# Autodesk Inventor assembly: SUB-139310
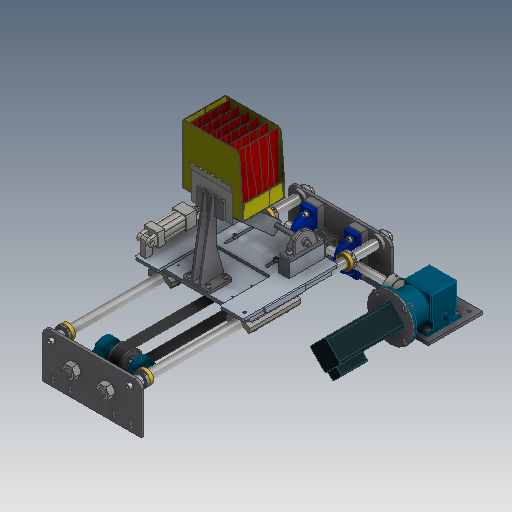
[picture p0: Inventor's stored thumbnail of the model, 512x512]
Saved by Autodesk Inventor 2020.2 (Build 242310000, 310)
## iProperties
Created: 1999-11
Part Number: SUB-139310
Document SubType Name: Assembly
Designer: sspink
Mass: 64674.3 g
Surface Area: 32419.9 cm^2
Volume: 15890.5 cm^3
Density: 4.07001 g/cm^3
Control State: 0
Master: False
Checked Out: False
Shininess: 0.0
Length Units: 11269
Angle Units: 11279
Time Units: 11290
Mass Units: 11283
Length Display Precision: 3
Angle Display Precision: 2
Compacted: True
Dimensions: 657,1x1021,6x696,7 mm
Mass: 64,674 kg
DocNumber: SUB-139310.iam
Folder: 01 - Themengebiete\Simplification\01 - Packaging machine\
VDS_Category: 3D Komponenten
Density: 0.0
Volumn: 0.0
Area: 0.0
PropertySet Name: Model Information
Author: sspink
Revision Number: -
Title: SUB-139310
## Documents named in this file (46)
- D:\07 - DEMODATEN\OTX 2019 - Dataset - UPDATE - Dez2019\Designs\07-Packing machine\SUB-139310.iam
- D:\07 - DEMODATEN\OTX 2019 - Dataset - UPDATE - Dez2019\Designs\07-Packing machine\500397.iam
- D:\07 - DEMODATEN\OTX 2019 - Dataset - UPDATE - Dez2019\Designs\07-Packing machine\Parts\ADSK-011320.ipt
- D:\07 - DEMODATEN\OTX 2019 - Dataset - UPDATE - Dez2019\Designs\07-Packing machine\Parts\ADSK-011732.ipt
- D:\07 - DEMODATEN\OTX 2019 - Dataset - UPDATE - Dez2019\Designs\07-Packing machine\Parts\ADSK-011289.ipt
- D:\07 - DEMODATEN\OTX 2019 - Dataset - UPDATE - Dez2019\Designs\07-Packing machine\Parts\ADSK-011687.ipt
- D:\07 - DEMODATEN\OTX 2019 - Dataset - UPDATE - Dez2019\Designs\07-Packing machine\500178.iam
- D:\07 - DEMODATEN\OTX 2019 - Dataset - UPDATE - Dez2019\Designs\07-Packing machine\Parts\ADSK-011294.ipt
- D:\07 - DEMODATEN\OTX 2019 - Dataset - UPDATE - Dez2019\Designs\07-Packing machine\A103577.iam
- D:\07 - DEMODATEN\OTX 2019 - Dataset - UPDATE - Dez2019\Designs\07-Packing machine\Parts\ADSK-011304.ipt
- D:\07 - DEMODATEN\OTX 2019 - Dataset - UPDATE - Dez2019\Designs\07-Packing machine\Parts\ADSK-011305.ipt
- D:\07 - DEMODATEN\OTX 2019 - Dataset - UPDATE - Dez2019\Designs\07-Packing machine\Parts\ADSK-011715.ipt
- D:\07 - DEMODATEN\OTX 2019 - Dataset - UPDATE - Dez2019\Designs\07-Packing machine\Parts\ADSK-011313.ipt
- D:\07 - DEMODATEN\OTX 2019 - Dataset - UPDATE - Dez2019\Designs\07-Packing machine\Parts\ADSK-011314.ipt
- D:\07 - DEMODATEN\OTX 2019 - Dataset - UPDATE - Dez2019\Designs\07-Packing machine\Parts\ADSK-011773.ipt
- D:\07 - DEMODATEN\OTX 2019 - Dataset - UPDATE - Dez2019\Designs\07-Packing machine\Parts\ADSK-011319.ipt
- D:\07 - DEMODATEN\OTX 2019 - Dataset - UPDATE - Dez2019\Designs\07-Packing machine\Parts\ADSK-011765.ipt
- D:\07 - DEMODATEN\OTX 2019 - Dataset - UPDATE - Dez2019\Designs\07-Packing machine\Parts\ADSK-011341.ipt
- D:\07 - DEMODATEN\OTX 2019 - Dataset - UPDATE - Dez2019\Designs\07-Packing machine\A103689.iam
- D:\07 - DEMODATEN\OTX 2019 - Dataset - UPDATE - Dez2019\Designs\07-Packing machine\Parts\ADSK-011342.ipt
- D:\07 - DEMODATEN\OTX 2019 - Dataset - UPDATE - Dez2019\Designs\07-Packing machine\Parts\ADSK-011753.ipt
- D:\07 - DEMODATEN\OTX 2019 - Dataset - UPDATE - Dez2019\Designs\07-Packing machine\Parts\ADSK-011234.ipt
- D:\07 - DEMODATEN\OTX 2019 - Dataset - UPDATE - Dez2019\Content Center Files\de-DE\DIN 125-1  B\DIN 125-1 - B 13.ipt
- D:\07 - DEMODATEN\OTX 2019 - Dataset - UPDATE - Dez2019\Content Center Files\de-DE\ISO 4762(2)\ISO 4762 - M12 x 25ISO.ipt
- D:\07 - DEMODATEN\OTX 2019 - Dataset - UPDATE - Dez2019\Content Center Files\de-DE\ISO 4762(2)\ISO 4762 - M6 x 20ISO.ipt
- D:\07 - DEMODATEN\OTX 2019 - Dataset - UPDATE - Dez2019\Designs\07-Packing machine\ADSK-014169.iam
- D:\07 - DEMODATEN\OTX 2019 - Dataset - UPDATE - Dez2019\Content Center Files\de-DE\DIN 125-1  B\DIN 125-1 - B 8,4.ipt
- D:\07 - DEMODATEN\OTX 2019 - Dataset - UPDATE - Dez2019\Content Center Files\de-DE\ISO 4762(2)\ISO 4762 - M8 x 20ISO.ipt
- D:\07 - DEMODATEN\OTX 2019 - Dataset - UPDATE - Dez2019\Content Center Files\de-DE\ISO 10642(1)\ISO 10642 - M6x10.ipt
- D:\07 - DEMODATEN\OTX 2019 - Dataset - UPDATE - Dez2019\Content Center Files\de-DE\DIN 125-1  B\DIN 125-1 - B 10,5.ipt
- D:\07 - DEMODATEN\OTX 2019 - Dataset - UPDATE - Dez2019\Content Center Files\de-DE\ISO 4762(2)\ISO 4762 - M10 x 30ISO.ipt
- D:\07 - DEMODATEN\OTX 2019 - Dataset - UPDATE - Dez2019\Content Center Files\de-DE\ISO 10642(1)\ISO 10642 - M8x20.ipt
- D:\07 - DEMODATEN\OTX 2019 - Dataset - UPDATE - Dez2019\Content Center Files\de-DE\ISO 4032(1)\ISO 4032 - M30DIN EN.ipt
- D:\07 - DEMODATEN\OTX 2019 - Dataset - UPDATE - Dez2019\Content Center Files\de-DE\ISO 2491 - A\ISO 2491 - A  6 x 4 x 32.ipt
- D:\07 - DEMODATEN\OTX 2019 - Dataset - UPDATE - Dez2019\Content Center Files\de-DE\ISO 2491 - A\ISO 2491 - A  6 x 4 x 28.ipt
- D:\07 - DEMODATEN\OTX 2019 - Dataset - UPDATE - Dez2019\Content Center Files\de-DE\ISO 10642(1)\ISO 10642 - M10x25.ipt
- D:\07 - DEMODATEN\OTX 2019 - Dataset - UPDATE - Dez2019\Content Center Files\de-DE\ISO 4032(1)\ISO 4032 - M10DIN EN.ipt
- D:\07 - DEMODATEN\OTX 2019 - Dataset - UPDATE - Dez2019\Designs\07-Packing machine\ADSK-014170.iam
- D:\07 - DEMODATEN\OTX 2019 - Dataset - UPDATE - Dez2019\Content Center Files\de-DE\ISO 2491 - A\ISO 2491 - A  6 x 4 x 40.ipt
- D:\07 - DEMODATEN\OTX 2019 - Dataset - UPDATE - Dez2019\Content Center Files\de-DE\ISO 4028\ISO 4028 - M8 x 20 - ISO.ipt
- D:\07 - DEMODATEN\OTX 2019 - Dataset - UPDATE - Dez2019\Content Center Files\de-DE\ISO 4028\ISO 4028 - M8 x 16 - ISO.ipt
- D:\07 - DEMODATEN\OTX 2019 - Dataset - UPDATE - Dez2019\Content Center Files\de-DE\ISO 4032(1)\ISO 4032 - M8DIN EN.ipt
- D:\07 - DEMODATEN\OTX 2019 - Dataset - UPDATE - Dez2019\Content Center Files\de-DE\ISO 4762(2)\ISO 4762 - M8 x 35ISO.ipt
- D:\07 - DEMODATEN\OTX 2019 - Dataset - UPDATE - Dez2019\Content Center Files\de-DE\ISO 4028\ISO 4028 - M5 x 10 - ISO.ipt
- D:\07 - DEMODATEN\OTX 2019 - Dataset - UPDATE - Dez2019\Designs\07-Packing machine\Parts\GMI 17 oz Pouch Tray.ipt
- GMI 17 oz Pouch Tray.ipt
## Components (119 placed, 44 different names)
1. ADSK-011319:1 — Insert:6, Insert:7, Mate:22, Mate:24, Flush:6
2. ADSK-011289:1 — Insert:7, Mate:17, Mate:47, Mate:49, Passend:56, Tangential:4
3. ADSK-011289:2 — Insert:6, Mate:16, Mate:46, Mate:48, Passend:55, Tangential:5
4. 500178:1 [sub-assembly] — Passend:60, Passend:61, Passend:62, Passend:63, Passend:64, Passend:65, Passend:68, Passend:70, Passend:72, Passend:74
5. ADSK-011294:1 — Passend:63, Passend:64, Passend:65, Passend:76, Passend:77, Passend:78, Passend:159
6. ADSK-011304:1 — Mate:5, Mate:7, Passend:15, Mate:25, Passend:112, Fluchtend:82, Passend:114, Passend:115, Passend:136, Passend:138, Fluchtend:89, Passend:141, Passend:142, Tangential:2
7. ADSK-011305:1 — Mate:32, Flush:5, Passend:130, Passend:132, Passend:133, Passend:135
8. ADSK-011715:3 — Mate:25, Mate:29, Passend:30, Passend:92, Passend:94, Passend:140
9. ADSK-011715:4 — Passend:15, Mate:28, Passend:31, Passend:88, Passend:90, Passend:139
10. ADSK-011314:1 — Insert:8, Mate:24, Flush:4
11. ADSK-011314:2 — Mate:22, Insert:21, Flush:4, Passend:107
12. ADSK-011773:1 — Insert:8, Flush:5
13. ADSK-011773:2 — Mate:32, Insert:21
14. ADSK-011313:1 — Mate:16, Mate:17, Insert:17, Insert:18, Insert:19, Insert:20, Flush:6, Insert:23, Insert:24, Insert:25, Insert:26, Passend:156, Passend:157
15. ADSK-011320:1 — Insert:19, Insert:20, Mate:28, Passend:139
16. ADSK-011320:2 — Insert:17, Insert:18, Mate:29, Passend:30, Passend:140
17. A103577:1 [sub-assembly] — Mate:1, Mate:2, Mate:3, Mate:4, Mate:6, Insert:1, Insert:15, Insert:16, Passend:143, Winkel:1, Passend:144, Passend:145, Tangential:3
18. ADSK-011765:1 — Insert:1
19. ADSK-011341:1 — Insert:13, Insert:14, Insert:15, Insert:16
20. A103689:1 [sub-assembly] — Insert:13, Insert:14
21. ADSK-011342:1 — Mate:1, Mate:2, Mate:3, Passend:143, Passend:144, Passend:145, Passend:149, Passend:151, Passend:153, Passend:155
22. ADSK-011753:1 — Mate:4, Mate:5, Mate:6, Mate:7, Fluchtend:82, Passend:116, Passend:146, Passend:147
23. ADSK-011234:1 — Passend:108, Fluchtend:86, Passend:131, Passend:137, Fluchtend:87, Fluchtend:89
24. 500397:1 [sub-assembly] — Passend:80, Fluchtend:81, Passend:82, Passend:84, Passend:108, Fluchtend:88, Passend:158, Tangential:6
25. ADSK-011732:1 — Insert:26
26. ADSK-011732:2 — Insert:23, Einfügen:40
27. ADSK-011732:3 — Insert:24, Einfügen:41
28. ADSK-011732:4 — Insert:25, Einfügen:42
29. ADSK-011732:5 — Mate:46, Flush:13, Insert:31, Einfügen:43
30. ADSK-011732:6 — Mate:47, Flush:13, Insert:32
31. ADSK-011732:7 — Mate:49, Flush:14, Insert:29
32. ADSK-011732:8 — Mate:48, Flush:14, Insert:30
33. GMI 17 oz Pouch Tray:2 — Passend:158, Passend:159, Tangential:6
34. ADSK-011687:1 — Insert:30
35. ADSK-011687:2 — Insert:29
36. ADSK-011687:3 — Insert:31
37. ADSK-011687:4 — Insert:32
38. ADSK-014169:1 [sub-assembly] — Passend:55, Passend:56, Passend:60, Passend:61, Passend:62, Passend:80, Fluchtend:81, Fluchtend:88
39. ADSK-014170:1 [sub-assembly] — Passend:130, Fluchtend:86, Passend:131, Passend:134, Passend:135
40. ADSK-014170:2 [sub-assembly] — Passend:136, Passend:137, Fluchtend:87, Passend:138
41. DIN 125-1 B B 8,4:7 — Passend:149
42. DIN 125-1 B B 8,4:8 — Passend:151
43. DIN 125-1 B B 8,4:9 — Passend:153
44. DIN 125-1 B B 8,4:10 — Passend:155
45. DIN 125-1 B B 8,4:11
46. DIN 125-1 B B 8,4:12
47. DIN 125-1 B B 8,4:13
48. DIN 125-1 B B 8,4:14
49. DIN EN 24032 M8:1
50. DIN EN 24032 M8:2
51. DIN EN 24032 M8:3
52. DIN EN 24032 M8:4
53. ISO 4762 M8 x 35:1
54. ISO 4762 M8 x 35:2
55. ISO 4762 M8 x 35:3
56. ISO 4762 M8 x 35:4
57. ISO 4028 M5 x 10:1 — Passend:156, Tangential:4
58. ISO 4028 M5 x 10:2 — Passend:157, Tangential:5
59. ISO 4028 M8 x 20:1 — Passend:146, Tangential:2
60. ISO 4028 M8 x 16:1 — Passend:147, Tangential:3
61. ISO 2491 A A  6 x 4 x 32:2 — Passend:132, Passend:133, Passend:134
62. DIN 125-1 B B 8,4:1 — Passend:68
63. DIN 125-1 B B 8,4:2 — Passend:70
64. DIN 125-1 B B 8,4:3 — Passend:72
65. DIN 125-1 B B 8,4:4 — Passend:74
66. ISO 4762 M8 x 20:1
67. ISO 4762 M8 x 20:2
68. ISO 4762 M8 x 20:3
69. ISO 4762 M8 x 20:4
70. ISO 10642 M6x10:1
71. ISO 10642 M6x10:2 — Passend:77
72. ISO 10642 M6x10:3 — Passend:76
73. ISO 10642 M6x10:4 — Passend:78
74. DIN 125-1 B B 8,4:5 — Passend:82
75. DIN 125-1 B B 8,4:6 — Passend:84, Passend:86
76. ISO 4762 M8 x 20:5 — Passend:86
77. ISO 4762 M8 x 20:6
78. DIN 125-1 B B 10,5:1 — Passend:88, Passend:96, Passend:98
79. DIN 125-1 B B 10,5:2 — Passend:90
80. DIN 125-1 B B 10,5:3 — Passend:92, Passend:100, Passend:102
81. DIN 125-1 B B 10,5:4 — Passend:94
82. ISO 4762 M10 x 30:1 — Passend:96
83. ISO 4762 M10 x 30:2 — Passend:98, Passend:31
84. ISO 4762 M10 x 30:3 — Passend:100
85. ISO 4762 M10 x 30:4 — Passend:102
86. ISO 10642 M8x20:1
87. ISO 10642 M8x20:2
88. ISO 10642 M8x20:3
89. ISO 10642 M8x20:4
90. DIN EN 24032 M30:1
91. DIN EN 24032 M30:2 — Passend:107
92. DIN EN 24032 M30:3
93. DIN EN 24032 M30:4
94. ISO 2491 A A  6 x 4 x 40:1 — Passend:112, Passend:141, Passend:142
95. ISO 2491 A A  6 x 4 x 28:1 — Passend:114, Passend:115, Passend:116
96. ISO 10642 M10x25:1
97. ISO 10642 M10x25:2
98. ISO 10642 M10x25:3
99. ISO 10642 M10x25:4
100. DIN 125-1 B B 10,5:5 — Passend:124
101. DIN 125-1 B B 10,5:6
102. DIN 125-1 B B 10,5:7
103. DIN 125-1 B B 10,5:8
104. DIN EN 24032 M10:1 — Passend:124
105. DIN EN 24032 M10:2
106. DIN EN 24032 M10:3
107. DIN EN 24032 M10:4
108. DIN 125-1 B B 13:1 — Passend:54
109. DIN 125-1 B B 13:2
110. ISO 4762 M12 x 25:1 — Passend:54
111. ISO 4762 M12 x 25:2
112. ISO 4762 M6 x 20:1
113. ISO 4762 M6 x 20:2
114. ISO 4762 M6 x 20:3
115. ISO 4762 M6 x 20:4
116. ISO 4762 M6 x 20:5 — Einfügen:40
117. ISO 4762 M6 x 20:6 — Einfügen:41
118. ISO 4762 M6 x 20:7 — Einfügen:42
119. ISO 4762 M6 x 20:8 — Einfügen:43
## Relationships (125: Mate 83, Insert 25, Flush 11, Tangent 5, Angle 1)
- Mate:1: A103577:1 ↔ ADSK-011342:1
- Mate:2: A103577:1 ↔ ADSK-011342:1
- Mate:3: A103577:1 ↔ ADSK-011342:1
- Mate:4: A103577:1 ↔ ADSK-011753:1
- Mate:5: ADSK-011304:1 ↔ ADSK-011753:1
- Mate:6: A103577:1 ↔ ADSK-011753:1
- Mate:7: ADSK-011304:1 ↔ ADSK-011753:1
- Insert:1: A103577:1 ↔ ADSK-011765:1
- Insert:6: ADSK-011319:1 ↔ ADSK-011289:2
- Insert:7: ADSK-011319:1 ↔ ADSK-011289:1
- Insert:8: ADSK-011314:1 ↔ ADSK-011773:1
- Passend:15 [Mate]: ADSK-011304:1 ↔ ADSK-011715:4
- Mate:16: ADSK-011289:2 ↔ ADSK-011313:1
- Mate:17: ADSK-011289:1 ↔ ADSK-011313:1
- Mate:22: ADSK-011319:1 ↔ ADSK-011314:2
- Mate:24: ADSK-011319:1 ↔ ADSK-011314:1
- Mate:25: ADSK-011304:1 ↔ ADSK-011715:3
- Insert:13: ADSK-011341:1 ↔ A103689:1
- Insert:14: ADSK-011341:1 ↔ A103689:1
- Insert:15: A103577:1 ↔ ADSK-011341:1
- Insert:16: A103577:1 ↔ ADSK-011341:1
- Insert:17: ADSK-011313:1 ↔ ADSK-011320:2
- Insert:18: ADSK-011313:1 ↔ ADSK-011320:2
- Insert:19: ADSK-011313:1 ↔ ADSK-011320:1
- Insert:20: ADSK-011313:1 ↔ ADSK-011320:1
- Mate:28: ADSK-011715:4 ↔ ADSK-011320:1
- Mate:29: ADSK-011715:3 ↔ ADSK-011320:2
- Passend:30 [Mate]: ADSK-011715:3 ↔ ADSK-011320:2
- Passend:31 [Mate]: ADSK-011715:4 ↔ ISO 4762 M10 x 30:2
- Mate:32: ADSK-011305:1 ↔ ADSK-011773:2
- Insert:21: ADSK-011314:2 ↔ ADSK-011773:2
- Flush:4: ADSK-011314:1 ↔ ADSK-011314:2
- Flush:5: ADSK-011305:1 ↔ ADSK-011773:1
- Flush:6: ADSK-011319:1 ↔ ADSK-011313:1
- Insert:23: ADSK-011313:1 ↔ ADSK-011732:2
- Insert:24: ADSK-011313:1 ↔ ADSK-011732:3
- Insert:25: ADSK-011313:1 ↔ ADSK-011732:4
- Insert:26: ADSK-011313:1 ↔ ADSK-011732:1
- Mate:46: ADSK-011289:2 ↔ ADSK-011732:5
- Mate:47: ADSK-011289:1 ↔ ADSK-011732:6
- Flush:13: ADSK-011732:5 ↔ ADSK-011732:6
- Mate:48: ADSK-011289:2 ↔ ADSK-011732:8
- Mate:49: ADSK-011289:1 ↔ ADSK-011732:7
- Flush:14: ADSK-011732:7 ↔ ADSK-011732:8
- Insert:29: ADSK-011732:7 ↔ ADSK-011687:2
- Insert:30: ADSK-011732:8 ↔ ADSK-011687:1
- Insert:31: ADSK-011732:5 ↔ ADSK-011687:3
- Insert:32: ADSK-011732:6 ↔ ADSK-011687:4
- Passend:54 [Mate]: DIN 125-1 B B 13:1 ↔ ISO 4762 M12 x 25:1
- Einfügen:40 [Insert]: ADSK-011732:2 ↔ ISO 4762 M6 x 20:5
- Einfügen:41 [Insert]: ADSK-011732:3 ↔ ISO 4762 M6 x 20:6
- Einfügen:42 [Insert]: ADSK-011732:4 ↔ ISO 4762 M6 x 20:7
- Einfügen:43 [Insert]: ADSK-011732:5 ↔ ISO 4762 M6 x 20:8
- Passend:55 [Mate]: ADSK-011289:2 ↔ ADSK-014169:1
- Passend:56 [Mate]: ADSK-011289:1 ↔ ADSK-014169:1
- Passend:60 [Mate]: 500178:1 ↔ ADSK-014169:1
- Passend:61 [Mate]: 500178:1 ↔ ADSK-014169:1
- Passend:62 [Mate]: 500178:1 ↔ ADSK-014169:1
- Passend:63 [Mate]: 500178:1 ↔ ADSK-011294:1
- Passend:64 [Mate]: 500178:1 ↔ ADSK-011294:1
- Passend:65 [Mate]: 500178:1 ↔ ADSK-011294:1
- Passend:68 [Mate]: 500178:1 ↔ DIN 125-1 B B 8,4:1
- Passend:70 [Mate]: 500178:1 ↔ DIN 125-1 B B 8,4:2
- Passend:72 [Mate]: 500178:1 ↔ DIN 125-1 B B 8,4:3
- Passend:74 [Mate]: 500178:1 ↔ DIN 125-1 B B 8,4:4
- Passend:76 [Mate]: ADSK-011294:1 ↔ ISO 10642 M6x10:3
- Passend:77 [Mate]: ADSK-011294:1 ↔ ISO 10642 M6x10:2
- Passend:78 [Mate]: ADSK-011294:1 ↔ ISO 10642 M6x10:4
- Passend:80 [Mate]: 500397:1 ↔ ADSK-014169:1
- Fluchtend:81 [Flush]: 500397:1 ↔ ADSK-014169:1
- Passend:82 [Mate]: 500397:1 ↔ DIN 125-1 B B 8,4:5
- Passend:84 [Mate]: 500397:1 ↔ DIN 125-1 B B 8,4:6
- Passend:86 [Mate]: DIN 125-1 B B 8,4:6 ↔ ISO 4762 M8 x 20:5
- Passend:88 [Mate]: ADSK-011715:4 ↔ DIN 125-1 B B 10,5:1
- Passend:90 [Mate]: ADSK-011715:4 ↔ DIN 125-1 B B 10,5:2
- Passend:92 [Mate]: ADSK-011715:3 ↔ DIN 125-1 B B 10,5:3
- Passend:94 [Mate]: ADSK-011715:3 ↔ DIN 125-1 B B 10,5:4
- Passend:96 [Mate]: DIN 125-1 B B 10,5:1 ↔ ISO 4762 M10 x 30:1
- Passend:98 [Mate]: DIN 125-1 B B 10,5:1 ↔ ISO 4762 M10 x 30:2
- Passend:100 [Mate]: DIN 125-1 B B 10,5:3 ↔ ISO 4762 M10 x 30:3
- Passend:102 [Mate]: DIN 125-1 B B 10,5:3 ↔ ISO 4762 M10 x 30:4
- Passend:107 [Mate]: ADSK-011314:2 ↔ DIN EN 24032 M30:2
- Passend:108 [Mate]: ADSK-011234:1 ↔ 500397:1
- Passend:112 [Mate]: ADSK-011304:1 ↔ ISO 2491 A A  6 x 4 x 40:1
- Fluchtend:82 [Flush]: ADSK-011304:1 ↔ ADSK-011753:1
- Passend:114 [Mate]: ADSK-011304:1 ↔ ISO 2491 A A  6 x 4 x 28:1
- Passend:115 [Mate]: ADSK-011304:1 ↔ ISO 2491 A A  6 x 4 x 28:1
- Passend:116 [Mate]: ADSK-011753:1 ↔ ISO 2491 A A  6 x 4 x 28:1
- Passend:124 [Mate]: DIN 125-1 B B 10,5:5 ↔ DIN EN 24032 M10:1
- Passend:130 [Mate]: ADSK-011305:1 ↔ ADSK-014170:1
- Fluchtend:86 [Flush]: ADSK-011234:1 ↔ ADSK-014170:1
- Passend:131 [Mate]: ADSK-011234:1 ↔ ADSK-014170:1
- Passend:132 [Mate]: ADSK-011305:1 ↔ ISO 2491 A A  6 x 4 x 32:2
- Passend:133 [Mate]: ADSK-011305:1 ↔ ISO 2491 A A  6 x 4 x 32:2
- Passend:134 [Mate]: ADSK-014170:1 ↔ ISO 2491 A A  6 x 4 x 32:2
- Passend:135 [Mate]: ADSK-011305:1 ↔ ADSK-014170:1
- Passend:136 [Mate]: ADSK-011304:1 ↔ ADSK-014170:2
- Passend:137 [Mate]: ADSK-011234:1 ↔ ADSK-014170:2
- Fluchtend:87 [Flush]: ADSK-011234:1 ↔ ADSK-014170:2
- Passend:138 [Mate]: ADSK-011304:1 ↔ ADSK-014170:2
- Passend:139 [Mate]: ADSK-011715:4 ↔ ADSK-011320:1
- Passend:140 [Mate]: ADSK-011715:3 ↔ ADSK-011320:2
- Fluchtend:88 [Flush]: 500397:1 ↔ ADSK-014169:1
- Fluchtend:89 [Flush]: ADSK-011304:1 ↔ ADSK-011234:1
- Passend:141 [Mate]: ADSK-011304:1 ↔ ISO 2491 A A  6 x 4 x 40:1
- Passend:142 [Mate]: ADSK-011304:1 ↔ ISO 2491 A A  6 x 4 x 40:1
- Passend:143 [Mate]: A103577:1 ↔ ADSK-011342:1
- Winkel:1 [Angle]: A103577:1
- Passend:144 [Mate]: A103577:1 ↔ ADSK-011342:1
- Passend:145 [Mate]: A103577:1 ↔ ADSK-011342:1
- Passend:146 [Mate]: ADSK-011753:1 ↔ ISO 4028 M8 x 20:1
- Passend:147 [Mate]: ADSK-011753:1 ↔ ISO 4028 M8 x 16:1
- Tangential:2: ADSK-011304:1 ↔ ISO 4028 M8 x 20:1
- Tangential:3: A103577:1 ↔ ISO 4028 M8 x 16:1
- Passend:149 [Mate]: ADSK-011342:1 ↔ DIN 125-1 B B 8,4:7
- Passend:151 [Mate]: ADSK-011342:1 ↔ DIN 125-1 B B 8,4:8
- Passend:153 [Mate]: ADSK-011342:1 ↔ DIN 125-1 B B 8,4:9
- Passend:155 [Mate]: ADSK-011342:1 ↔ DIN 125-1 B B 8,4:10
- Passend:156 [Mate]: ADSK-011313:1 ↔ ISO 4028 M5 x 10:1
- Tangential:4: ADSK-011289:1 ↔ ISO 4028 M5 x 10:1
- Passend:157 [Mate]: ADSK-011313:1 ↔ ISO 4028 M5 x 10:2
- Tangential:5: ADSK-011289:2 ↔ ISO 4028 M5 x 10:2
- Passend:158 [Mate]: 500397:1 ↔ GMI 17 oz Pouch Tray:2
- Passend:159 [Mate]: ADSK-011294:1 ↔ GMI 17 oz Pouch Tray:2
- Tangential:6: 500397:1 ↔ GMI 17 oz Pouch Tray:2
## Named parameters: width = 165.1 mm
